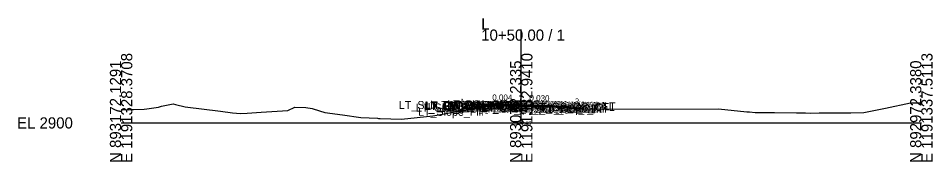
# Model space of a CAD drawing. Extents: x -26 to 203, y -10 to 7027.
# Drawn here: x -25.7 to 202.8, y 990.3 to 1026.2 of the extents above; entities that cross this region are included whole.
import ezdxf

# ---------------------------------------------------------------- set-up
doc = ezdxf.new("R2010")
doc.units = 0
for name, color, linetype in [('Default', 7, 'Continuous'), ('Exist CMT Pavement', 7, 'Continuous'), ('Exist Cross Section Cell', 7, 'Continuous'), ('Exist XS Center Line Elevation Label', 7, 'Continuous'), ('Exist XS Ground Line', 7, 'Continuous'), ('Prop CMT Concrete Structures', 7, 'Continuous'), ('Prop CMT Pvmt Course 1', 7, 'Continuous'), ('Prop CMT Pvmt Course 2', 7, 'Continuous'), ('Prop CMT Pvmt Course 2 Wedge', 7, 'Continuous'), ('Prop CMT Pvmt Course 3', 7, 'Continuous'), ('Prop CMT Pvmt Course 3 Wedge', 7, 'Continuous'), ('Prop CMT Pvmt Surface', 7, 'Continuous'), ('Prop CMT Pvmt Surface Shoulder', 7, 'Continuous'), ('Prop CMT Pvmt Wedge Surface 3', 7, 'Continuous'), ('Prop CMT Shld Paved Course 1', 7, 'Continuous'), ('Prop CMT Shld Paved Course 2', 7, 'Continuous'), ('Prop CMT Shld Paved Course 3', 7, 'Continuous'), ('Prop CMT Slope Grass', 7, 'Continuous'), ('Prop CMT Subgrade Earthwork', 7, 'Continuous'), ('Scratch_Level_6', 7, 'Continuous')]:
    doc.layers.add(name, color=color, linetype=linetype)

msp = doc.modelspace()

# ---------------------------------------------------------------- linework, layer by layer
at = {"layer": 'Exist CMT Pavement'}
for points in [[(90.75, 1004.42), (90.54, 1004.42), (90.32, 1004.2)], [(90.32, 1004.2), (90.75, 1004.21)], [(90.75, 1004.21), (90.75, 1004.42)], [(100, 1004.46), (90.93, 1004.42)], [(90.93, 1004.42), (95.46, 1004.44)], [(95.46, 1004.44), (100, 1004.46)], [(104.63, 1004.33), (100, 1004.46)], [(100, 1004.46), (109.25, 1004.19)], [(109.25, 1004.19), (104.63, 1004.33)], [(109.25, 1004.1), (109.46, 1004.1), (109.68, 1003.89)], [(109.25, 1003.9), (109.25, 1004.1)], [(109.68, 1003.89), (109.25, 1003.9)]]:
    msp.add_lwpolyline(points, dxfattribs=at)
at = {"layer": 'Exist Cross Section Cell'}
for p, q in [((100, 1000), (100, 1023.35)), ((0, 1000), (100, 1000)), ((100, 1000), (200, 1000))]:
    msp.add_line(p, q, dxfattribs=at)
at = {"layer": 'Exist XS Center Line Elevation Label'}
for points in [[(100, 1004.38), (90.93, 1004.42)], [(100, 1004.38), (109.25, 1004.1)]]:
    msp.add_lwpolyline(points, dxfattribs=at)
at = {"layer": 'Exist XS Ground Line'}
for points in [[(100, 1004.47), (90.93, 1004.5)], [(100, 1004.47), (109.25, 1004.19)]]:
    msp.add_lwpolyline(points, dxfattribs=at)
at = {"layer": 'Prop CMT Concrete Structures'}
for points in [[(100, 1004.59), (90.75, 1004.63)], [(100, 1004.59), (109.25, 1004.31)]]:
    msp.add_lwpolyline(points, dxfattribs=at)
at = {"layer": 'Prop CMT Pvmt Course 1'}
for points in [[(100, 1004.59), (90.75, 1004.63)], [(90.75, 1004.63), (90.75, 1004.42)], [(90.75, 1004.42), (90.93, 1004.42)], [(90.93, 1004.42), (90.75, 1004.42)], [(90.75, 1004.42), (90.75, 1004.21)], [(90.75, 1004.21), (90.93, 1004.21)], [(90.93, 1004.42), (90.93, 1004.5)], [(90.93, 1004.5), (100, 1004.47)], [(90.93, 1004.21), (90.93, 1004.42)], [(100, 1004.38), (100, 1004.59)], [(100, 1004.59), (109.25, 1004.31)], [(100, 1004.38), (100, 1004.59)], [(100, 1004.47), (100, 1004.38), (100, 1004.38)], [(109.25, 1004.19), (100, 1004.47)], [(100, 1004.47), (100, 1004.38), (100, 1004.38)], [(109.25, 1004.31), (109.25, 1004.1), (109.25, 1004.1), (109.25, 1004.19)], [(109.25, 1003.9), (109.25, 1003.9), (109.25, 1004.1), (109.25, 1004.1)], [(109.25, 1004.1), (109.25, 1003.9)]]:
    msp.add_lwpolyline(points, dxfattribs=at)
at = {"layer": 'Prop CMT Pvmt Course 2'}
for points in [[(100, 1004.17), (90.93, 1004.21)], [(100, 1004.17), (109.25, 1003.9)]]:
    msp.add_lwpolyline(points, dxfattribs=at)
at = {"layer": 'Prop CMT Pvmt Course 3'}
for points in [[(90.93, 1004.21), (90.75, 1004.21)], [(90.75, 1004.21), (90.75, 1003.88)], [(90.75, 1003.88), (90.93, 1003.88)], [(90.93, 1003.88), (90.93, 1004.21)], [(109.25, 1003.9), (109.25, 1003.9), (109.25, 1003.56), (109.25, 1003.56)], [(109.25, 1003.56), (109.25, 1003.9)]]:
    msp.add_lwpolyline(points, dxfattribs=at)
at = {"layer": 'Prop CMT Pvmt Course 3 Wedge'}
for p, q in [((0, 1003.32), (1.81, 1003.31)), ((1.81, 1003.31), (2.35, 1003.32)), ((2.35, 1003.32), (3.09, 1003.33)), ((3.09, 1003.33), (5.74, 1003.45)), ((5.74, 1003.45), (6.47, 1003.55)), ((6.47, 1003.55), (7, 1003.62)), ((7, 1003.62), (8.77, 1003.87)), ((8.77, 1003.87), (9.32, 1003.96)), ((9.32, 1003.96), (10.09, 1004.18)), ((10.09, 1004.18), (11.76, 1004.54)), ((11.76, 1004.54), (13.04, 1004.81)), ((13.04, 1004.81), (13.62, 1004.64)), ((13.62, 1004.64), (16.02, 1004.03)), ((16.02, 1004.03), (24.84, 1002.9)), ((41.71, 1003.11), (43.38, 1003.92)), ((43.38, 1003.92), (46.21, 1003.88)), ((46.21, 1003.88), (47.76, 1003.61)), ((47.76, 1003.61), (49.62, 1003.05)), ((82.07, 1002.49), (87.55, 1003.47)), ((87.55, 1003.47), (88.43, 1003.72)), ((88.43, 1003.72), (90.93, 1004.42)), ((90.93, 1004.42), (94.25, 1004.43)), ((94.25, 1004.43), (100.18, 1004.46)), ((100.18, 1004.46), (103.96, 1004.35)), ((103.96, 1004.35), (109.56, 1004.18)), ((109.56, 1004.18), (113.17, 1003.69)), ((113.17, 1003.69), (114.81, 1003.47)), ((114.81, 1003.47), (118.23, 1003.52)), ((118.23, 1003.52), (122.69, 1003.42)), ((122.69, 1003.42), (149.33, 1003.53)), ((149.33, 1003.53), (156.37, 1002.8)), ((185.63, 1002.57), (191, 1003.68)), ((191, 1003.68), (197.3, 1005.01)), ((197.3, 1005.01), (198.89, 1005.01)), ((198.89, 1005.01), (200, 1005)), ((24.84, 1002.9), (27.85, 1002.55)), ((27.85, 1002.55), (29.86, 1002.36)), ((29.86, 1002.36), (31.55, 1002.45)), ((31.55, 1002.45), (35, 1002.67)), ((35, 1002.67), (41.71, 1003.11)), ((49.62, 1003.05), (50.88, 1002.58)), ((50.88, 1002.58), (55.34, 1002.03)), ((55.34, 1002.03), (59.88, 1001.38)), ((59.88, 1001.38), (64.04, 1001.15)), ((64.04, 1001.15), (64.35, 1001.12)), ((64.35, 1001.12), (64.72, 1001.11)), ((64.72, 1001.11), (70.06, 1000.91)), ((70.06, 1000.91), (77.91, 1001.81)), ((77.91, 1001.81), (78.87, 1001.95)), ((78.87, 1001.95), (82.07, 1002.49)), ((156.37, 1002.8), (157.02, 1002.75)), ((157.02, 1002.75), (158.46, 1002.62)), ((158.46, 1002.62), (163.3, 1002.61)), ((163.3, 1002.61), (168.8, 1002.53)), ((168.8, 1002.53), (171.05, 1002.49)), ((171.05, 1002.49), (172.28, 1002.48)), ((172.28, 1002.48), (174.48, 1002.51)), ((174.48, 1002.51), (179.22, 1002.53)), ((179.22, 1002.53), (181.01, 1002.54)), ((181.01, 1002.54), (182.34, 1002.55)), ((182.34, 1002.55), (185.63, 1002.57))]:
    msp.add_line(p, q, dxfattribs=at)
at = {"layer": 'Prop CMT Pvmt Surface'}
for points in [[(90.75, 1004.63), (86.75, 1004.31), (83.7, 1002.78)], [(109.25, 1004.31), (113.25, 1003.99), (114.11, 1003.56)]]:
    msp.add_lwpolyline(points, dxfattribs=at)
at = {"layer": 'Prop CMT Pvmt Surface Shoulder'}
for points in [[(90.75, 1004.63), (90.75, 1004.63)], [(109.25, 1004.31), (109.25, 1004.31)]]:
    msp.add_lwpolyline(points, dxfattribs=at)
at = {"layer": 'Prop CMT Shld Paved Course 1'}
for points in [[(90.75, 1004.63), (90.54, 1004.42)], [(90.54, 1004.42), (90.75, 1004.42)], [(90.75, 1004.63), (90.75, 1004.63)], [(90.75, 1004.42), (90.75, 1004.63)], [(90.75, 1004.42), (90.75, 1004.63)], [(90.93, 1004.42), (90.75, 1004.42)], [(100, 1004.47), (90.93, 1004.5)], [(90.93, 1004.5), (90.93, 1004.42)], [(100, 1004.47), (109.25, 1004.19)], [(109.25, 1004.31), (109.25, 1004.31)], [(109.25, 1004.31), (109.46, 1004.1)], [(109.25, 1004.1), (109.25, 1004.31)], [(109.25, 1004.1), (109.25, 1004.31)], [(109.25, 1004.19), (109.25, 1004.1), (109.25, 1004.1)], [(109.46, 1004.1), (109.25, 1004.1)]]:
    msp.add_lwpolyline(points, dxfattribs=at)
at = {"layer": 'Prop CMT Shld Paved Course 2'}
for points in [[(90.75, 1004.42), (90.75, 1004.63)], [(100, 1004.38), (90.75, 1004.42)], [(100, 1004.38), (109.25, 1004.1)], [(109.25, 1004.1), (109.25, 1004.31)]]:
    msp.add_lwpolyline(points, dxfattribs=at)
at = {"layer": 'Prop CMT Shld Paved Course 3'}
for points in [[(90.75, 1004.21), (90.75, 1004.63)], [(100, 1004.17), (90.75, 1004.21)], [(100, 1004.17), (109.25, 1003.9)], [(109.25, 1003.9), (109.25, 1004.31)]]:
    msp.add_lwpolyline(points, dxfattribs=at)
at = {"layer": 'Prop CMT Slope Grass'}
for points in [[(90.75, 1004.21), (90.32, 1004.2), (89.82, 1004.19), (89.48, 1003.85)], [(89.48, 1003.85), (90.75, 1003.88)], [(90.75, 1003.88), (90.75, 1004.21)], [(109.25, 1003.9), (109.68, 1003.89), (110.18, 1003.88), (110.52, 1003.54)], [(109.25, 1003.56), (109.25, 1003.9)], [(110.52, 1003.54), (109.25, 1003.56)]]:
    msp.add_lwpolyline(points, dxfattribs=at)
at = {"layer": 'Prop CMT Subgrade Earthwork'}
for points in [[(89.48, 1003.85), (88.86, 1004.48)], [(90.75, 1003.88), (89.48, 1003.85)], [(90.93, 1003.88), (90.75, 1003.88)], [(90.93, 1003.88), (90.94, 1004.42)], [(109.25, 1003.56), (109.24, 1004.19)], [(109.25, 1003.56), (109.25, 1003.56)], [(109.25, 1003.56), (110.52, 1003.54)], [(110.52, 1003.54), (111.14, 1004.16)]]:
    msp.add_lwpolyline(points, dxfattribs=at)

# ---------------------------------------------------------------- texts
at = {"layer": 'Default'}
msp.add_text('-', height=0.0001, dxfattribs=at).set_placement((0, 1000))
at = {"layer": 'Exist Cross Section Cell'}
for s, p in [('L', (90, 1023.35)), ('10+50.00 / 1', (90, 1020.55)), ('EL 2900', (-26, 998.6))]:
    msp.add_text(s, height=2.8, dxfattribs=at).set_placement(p)
for s, p in [('E 1191328.3708', (2.8, 990)), ('E 1191332.9410', (102.8, 990)), ('E 1191337.5113', (202.8, 990)), ('N 893172.1291', (0, 990)), ('N 893072.2335', (100, 990)), ('N 892972.3380', (200, 990))]:
    msp.add_text(s, height=2.8, rotation=90, dxfattribs=at).set_placement(p)
at = {"layer": 'Prop CMT Pvmt Course 2 Wedge'}
for s, p in [('LT_Sub_Trench_Out_DLT', (69.43, 1003.48)), ('LT_PV1_OEOT', (81.49, 1003.63)), ('LT_PS1_OEOP', (81.55, 1003.63)), ('PV1_PGL', (94.47, 1003.59)), ('LT_Sub_Trench_Out', (73.69, 1002.85)), ('LT_Slope_Fill', (74.22, 1001.78)), ('LT_PS3_Shelf_Out', (75.81, 1003.19)), ('LT_PV_Sub_Tie_Out', (75.89, 1003.42)), ('LT_GS_OS_CTL', (76.12, 1003.31)), ('LT_PV_OEEOP_EG', (78.47, 1003.42)), ('LT_Sub_OEEOP', (80.14, 1002.88)), ('LT_PV2_OEEOP', (80.23, 1003.42)), ('LT_PV3_OEEOP', (80.23, 1003.21)), ('LT_PS3_OEOP', (80.56, 1003.2)), ('LT_PS2_OEOP', (80.77, 1003.42)), ('LT_PV1_OEEOP', (80.8, 1003.5)), ('LT_Sub_OEOT', (80.83, 1002.88)), ('LT_PV2_OEOT', (80.92, 1003.42)), ('LT_PV3_OEOT', (80.92, 1003.21)), ('LT_PV_EG_TestPt', (81.87, 1003.44)), ('RT_PV_IEEOP_EG', (88.14, 1003.46)), ('LT_PV_IEEOP_EG', (88.19, 1003.46)), ('RT_PV2_IEEOP', (89.91, 1003.38)), ('RT_PV3_IEEOP', (89.91, 1003.17)), ('LT_PV2_IEEOP', (89.95, 1003.38)), ('LT_PV3_IEEOP', (89.95, 1003.17)), ('RT_PV1_IEEOP', (90.47, 1003.47)), ('LT_PV1_IEEOP', (90.52, 1003.47)), ('RT_PV_EG_TestPt', (90.99, 1003.33)), ('RT_Sub_Trench_Out_DLT', (91.66, 1003.16)), ('PV2_PGL', (93.91, 1003.38)), ('RT_PV_Sub_Tie_Out', (94.13, 1003.19)), ('RT_Sub_Trench_Out', (94.67, 1002.54)), ('RT_PS3_Shelf_Out', (96.11, 1002.88)), ('RT_PV_OEEOP_EG', (96.75, 1003.19)), ('RT_Sub_OEEOP', (98.42, 1002.56)), ('RT_PV2_OEEOP', (98.51, 1003.1)), ('RT_PV3_OEEOP', (98.51, 1002.9)), ('RT_PV1_OEEOP', (99.08, 1003.19)), ('RT_Sub_OEOT', (99.28, 1002.56)), ('RT_PV2_OEOT', (99.38, 1003.1)), ('RT_PV3_OEOT', (99.38, 1002.9)), ('RT_PS2_OEOP', (99.65, 1003.1)), ('RT_PS3_OEOP', (99.86, 1002.89)), ('RT_PV1_OEOT', (99.94, 1003.31)), ('RT_PS1_OEOP', (100.01, 1003.31)), ('RT_GS_OS_CTL', (102.57, 1002.99)), ('RT_Slope_Fill', (104.58, 1002.56))]:
    msp.add_text(s, height=2, dxfattribs=at).set_placement(p)
at = {"layer": 'Prop CMT Pvmt Surface Shoulder'}
for s, rotation, p in [('0.004', 359.7651, (92.76, 1005.62)), ('0.030', 358.2816, (102.03, 1005.53))]:
    msp.add_text(s, height=1.5, rotation=rotation, dxfattribs=at).set_placement(p)
at = {"layer": 'Prop CMT Pvmt Wedge Surface 3'}
for rotation, p in [(26.5651, (83.83, 1003.69)), (333.4349, (112.95, 1004.98))]:
    msp.add_text('2:1', height=1.5, rotation=rotation, dxfattribs=at).set_placement(p)
at = {"layer": 'Scratch_Level_6'}
msp.add_text('2904.46', height=1, dxfattribs=at).set_placement((97.51, 999.46))

doc.saveas('drawing.dxf')
